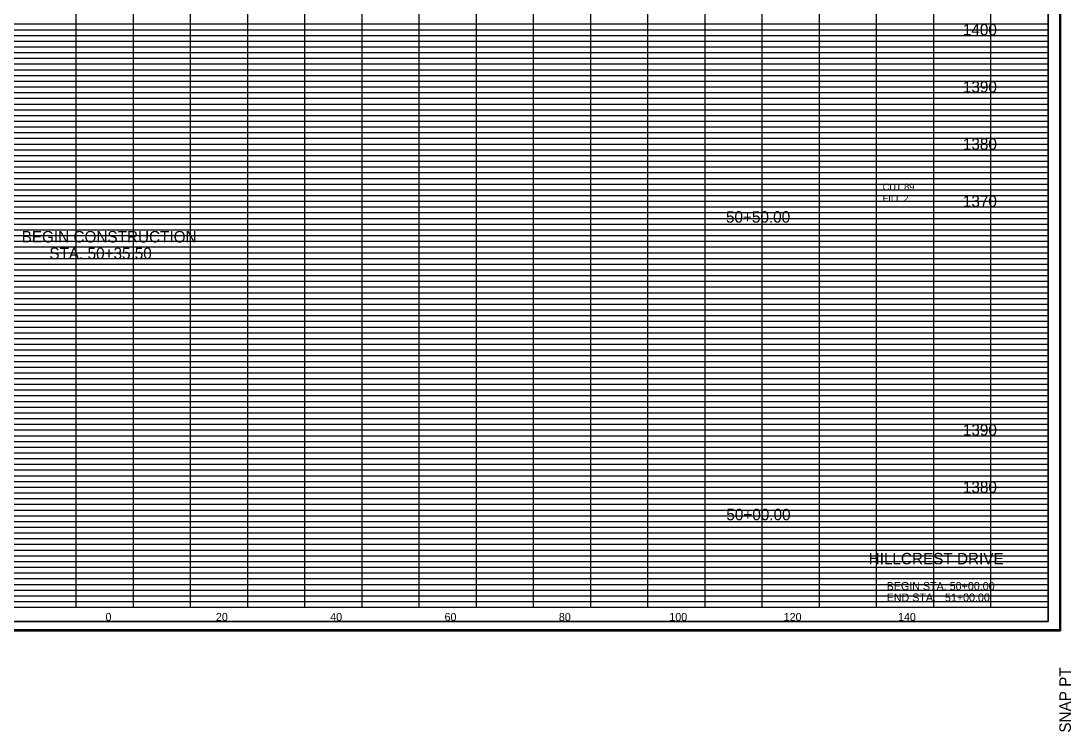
# Model space of a CAD drawing. Extents: x 980 to 1324, y 978 to 1497.
# Drawn here: x 1140.3 to 1324, y 978.2 to 1102.5 of the extents above; entities that cross this region are included whole.
import ezdxf

# ---------------------------------------------------------------- set-up
doc = ezdxf.new("R2010")
doc.units = 0
for name, color, linetype in [('DESIGN - SHEET - Corner Text', 7, 'Continuous'), ('DESIGN - SHEET - Light Grid', 7, 'Continuous'), ('DESIGN - SHEET - Linework', 7, 'Continuous'), ('DESIGN - SHEET - Plot Shape', 7, 'Continuous'), ('DESIGN - TYPICAL - Text', 7, 'Continuous')]:
    doc.layers.add(name, color=color, linetype=linetype)

# ---------------------------------------------------------------- blocks, each defined once
blk = doc.blocks.new('XSTSHT')
at = {"layer": 'DESIGN - SHEET - Light Grid'}
for p, q in [((8, 10.2), (16, 10.2)), ((16, 10.2), (24, 10.2)), ((24, 10.2), (32, 10.2)), ((8, 10.1), (16, 10.1)), ((16, 10.1), (24, 10.1)), ((24, 10.1), (32, 10.1)), ((8, 9.9), (16, 9.9)), ((8, 9.8), (16, 9.8)), ((16, 9.9), (24, 9.9)), ((16, 9.8), (24, 9.8)), ((24, 9.9), (32, 9.9)), ((24, 9.8), (32, 9.8)), ((8, 9.7), (16, 9.7)), ((8, 9.6), (16, 9.6)), ((16, 9.7), (24, 9.7)), ((16, 9.6), (24, 9.6)), ((24, 9.7), (32, 9.7)), ((24, 9.6), (32, 9.6)), ((8, 9.5), (16, 9.5)), ((8, 9.4), (16, 9.4)), ((16, 9.5), (24, 9.5)), ((16, 9.4), (24, 9.4)), ((24, 9.5), (32, 9.5)), ((24, 9.4), (32, 9.4)), ((8, 9.3), (16, 9.3)), ((8, 9.2), (16, 9.2)), ((16, 9.3), (24, 9.3)), ((16, 9.2), (24, 9.2)), ((24, 9.3), (32, 9.3)), ((24, 9.2), (32, 9.2)), ((8, 9.1), (16, 9.1)), ((16, 9.1), (24, 9.1)), ((24, 9.1), (32, 9.1)), ((8, 8.9), (16, 8.9)), ((16, 8.9), (24, 8.9)), ((24, 8.9), (32, 8.9)), ((8, 8.8), (16, 8.8)), ((8, 8.7), (16, 8.7)), ((16, 8.8), (24, 8.8)), ((16, 8.7), (24, 8.7)), ((24, 8.8), (32, 8.8)), ((24, 8.7), (32, 8.7)), ((8, 8.6), (16, 8.6)), ((8, 8.5), (16, 8.5)), ((16, 8.6), (24, 8.6)), ((16, 8.5), (24, 8.5)), ((24, 8.6), (32, 8.6)), ((24, 8.5), (32, 8.5)), ((8, 8.4), (16, 8.4)), ((8, 8.3), (16, 8.3)), ((16, 8.4), (24, 8.4)), ((16, 8.3), (24, 8.3)), ((24, 8.4), (32, 8.4)), ((24, 8.3), (32, 8.3)), ((8, 8.2), (16, 8.2)), ((8, 8.1), (16, 8.1)), ((16, 8.2), (24, 8.2)), ((16, 8.1), (24, 8.1)), ((24, 8.2), (32, 8.2)), ((24, 8.1), (32, 8.1)), ((8, 7.9), (16, 7.9)), ((16, 7.9), (24, 7.9)), ((24, 7.9), (32, 7.9)), ((8, 7.8), (16, 7.8)), ((16, 7.8), (24, 7.8)), ((24, 7.8), (32, 7.8)), ((8, 7.7), (16, 7.7)), ((8, 7.6), (16, 7.6)), ((16, 7.7), (24, 7.7)), ((16, 7.6), (24, 7.6)), ((24, 7.7), (32, 7.7)), ((24, 7.6), (32, 7.6)), ((8, 7.5), (16, 7.5)), ((8, 7.4), (16, 7.4)), ((16, 7.5), (24, 7.5)), ((16, 7.4), (24, 7.4)), ((24, 7.5), (32, 7.5)), ((24, 7.4), (32, 7.4)), ((8, 7.3), (16, 7.3)), ((8, 7.2), (16, 7.2)), ((16, 7.3), (24, 7.3)), ((16, 7.2), (24, 7.2)), ((24, 7.3), (32, 7.3)), ((24, 7.2), (32, 7.2)), ((8, 7.1), (16, 7.1)), ((16, 7.1), (24, 7.1)), ((24, 7.1), (32, 7.1)), ((8, 6.9), (16, 6.9)), ((8, 6.8), (16, 6.8)), ((16, 6.9), (24, 6.9)), ((16, 6.8), (24, 6.8)), ((24, 6.9), (32, 6.9)), ((24, 6.8), (32, 6.8)), ((8, 6.7), (16, 6.7)), ((16, 6.7), (24, 6.7)), ((24, 6.7), (32, 6.7)), ((8, 6.6), (16, 6.6)), ((8, 6.5), (16, 6.5)), ((16, 6.6), (24, 6.6)), ((16, 6.5), (24, 6.5)), ((24, 6.6), (32, 6.6)), ((24, 6.5), (32, 6.5)), ((8, 6.4), (16, 6.4)), ((8, 6.3), (16, 6.3)), ((16, 6.4), (24, 6.4)), ((16, 6.3), (24, 6.3)), ((24, 6.4), (32, 6.4)), ((24, 6.3), (32, 6.3)), ((8, 6.2), (16, 6.2)), ((8, 6.1), (16, 6.1)), ((16, 6.2), (24, 6.2)), ((16, 6.1), (24, 6.1)), ((24, 6.2), (32, 6.2)), ((24, 6.1), (32, 6.1)), ((8, 5.9), (16, 5.9)), ((16, 5.9), (24, 5.9)), ((24, 5.9), (32, 5.9)), ((8, 5.8), (16, 5.8)), ((8, 5.7), (16, 5.7)), ((16, 5.8), (24, 5.8)), ((16, 5.7), (24, 5.7)), ((24, 5.8), (32, 5.8)), ((24, 5.7), (32, 5.7)), ((8, 5.6), (16, 5.6)), ((16, 5.6), (24, 5.6)), ((24, 5.6), (32, 5.6)), ((8, 5.5), (16, 5.5)), ((8, 5.4), (16, 5.4)), ((16, 5.5), (24, 5.5)), ((16, 5.4), (24, 5.4)), ((24, 5.5), (32, 5.5)), ((24, 5.4), (32, 5.4)), ((8, 5.3), (16, 5.3)), ((8, 5.2), (16, 5.2)), ((16, 5.3), (24, 5.3)), ((16, 5.2), (24, 5.2)), ((24, 5.3), (32, 5.3)), ((24, 5.2), (32, 5.2)), ((8, 5.1), (16, 5.1)), ((16, 5.1), (24, 5.1)), ((24, 5.1), (32, 5.1)), ((8, 4.9), (16, 4.9)), ((8, 4.8), (16, 4.8)), ((16, 4.9), (24, 4.9)), ((16, 4.8), (24, 4.8)), ((24, 4.9), (32, 4.9)), ((24, 4.8), (32, 4.8)), ((8, 4.7), (16, 4.7)), ((8, 4.6), (16, 4.6)), ((16, 4.7), (24, 4.7)), ((16, 4.6), (24, 4.6)), ((24, 4.7), (32, 4.7)), ((24, 4.6), (32, 4.6)), ((8, 4.5), (16, 4.5)), ((16, 4.5), (24, 4.5)), ((24, 4.5), (32, 4.5)), ((8, 4.4), (16, 4.4)), ((8, 4.3), (16, 4.3)), ((16, 4.4), (24, 4.4)), ((16, 4.3), (24, 4.3)), ((24, 4.4), (32, 4.4)), ((24, 4.3), (32, 4.3)), ((8, 4.2), (16, 4.2)), ((8, 4.1), (16, 4.1)), ((16, 4.2), (24, 4.2)), ((16, 4.1), (24, 4.1)), ((24, 4.2), (32, 4.2)), ((24, 4.1), (32, 4.1)), ((8, 3.9), (16, 3.9)), ((16, 3.9), (24, 3.9)), ((24, 3.9), (32, 3.9)), ((8, 3.8), (16, 3.8)), ((8, 3.7), (16, 3.7)), ((16, 3.8), (24, 3.8)), ((16, 3.7), (24, 3.7)), ((24, 3.8), (32, 3.8)), ((24, 3.7), (32, 3.7)), ((8, 3.6), (16, 3.6)), ((8, 3.5), (16, 3.5)), ((16, 3.6), (24, 3.6)), ((16, 3.5), (24, 3.5)), ((24, 3.6), (32, 3.6)), ((24, 3.5), (32, 3.5)), ((8, 3.4), (16, 3.4)), ((16, 3.4), (24, 3.4)), ((24, 3.4), (32, 3.4)), ((8, 3.3), (16, 3.3)), ((8, 3.2), (16, 3.2)), ((16, 3.3), (24, 3.3)), ((16, 3.2), (24, 3.2)), ((24, 3.3), (32, 3.3)), ((24, 3.2), (32, 3.2)), ((8, 3.1), (16, 3.1)), ((16, 3.1), (24, 3.1)), ((24, 3.1), (32, 3.1)), ((8, 2.9), (16, 2.9)), ((8, 2.8), (16, 2.8)), ((16, 2.9), (24, 2.9)), ((16, 2.8), (24, 2.8)), ((24, 2.9), (32, 2.9)), ((24, 2.8), (32, 2.8)), ((8, 2.7), (16, 2.7)), ((8, 2.6), (16, 2.6)), ((16, 2.7), (24, 2.7)), ((16, 2.6), (24, 2.6)), ((24, 2.7), (32, 2.7)), ((24, 2.6), (32, 2.6)), ((8, 2.5), (16, 2.5)), ((8, 2.4), (16, 2.4)), ((16, 2.5), (24, 2.5)), ((16, 2.4), (24, 2.4)), ((24, 2.5), (32, 2.5)), ((24, 2.4), (32, 2.4)), ((8, 2.3), (16, 2.3)), ((16, 2.3), (24, 2.3)), ((24, 2.3), (32, 2.3)), ((8, 2.2), (16, 2.2)), ((8, 2.1), (16, 2.1)), ((16, 2.2), (24, 2.2)), ((16, 2.1), (24, 2.1)), ((24, 2.2), (32, 2.2)), ((24, 2.1), (32, 2.1)), ((8, 1.9), (16, 1.9)), ((16, 1.9), (24, 1.9)), ((24, 1.9), (32, 1.9)), ((8, 1.8), (16, 1.8)), ((8, 1.7), (16, 1.7)), ((16, 1.8), (24, 1.8)), ((16, 1.7), (24, 1.7)), ((24, 1.8), (32, 1.8)), ((24, 1.7), (32, 1.7)), ((8, 1.6), (16, 1.6)), ((8, 1.5), (16, 1.5)), ((16, 1.6), (24, 1.6)), ((16, 1.5), (24, 1.5)), ((24, 1.6), (32, 1.6)), ((24, 1.5), (32, 1.5)), ((8, 1.4), (16, 1.4)), ((8, 1.3), (16, 1.3)), ((16, 1.4), (24, 1.4)), ((16, 1.3), (24, 1.3)), ((24, 1.4), (32, 1.4)), ((24, 1.3), (32, 1.3)), ((8, 1.2), (16, 1.2)), ((16, 1.2), (24, 1.2)), ((24, 1.2), (32, 1.2)), ((8, 1.1), (16, 1.1)), ((16, 1.1), (24, 1.1)), ((24, 1.1), (32, 1.1)), ((8, 0.9), (16, 0.9)), ((8, 0.8), (16, 0.8)), ((16, 0.9), (24, 0.9)), ((16, 0.8), (24, 0.8)), ((24, 0.9), (32, 0.9)), ((24, 0.8), (32, 0.8)), ((8, 0.7), (16, 0.7)), ((8, 0.6), (16, 0.6)), ((16, 0.7), (24, 0.7)), ((16, 0.6), (24, 0.6)), ((24, 0.7), (32, 0.7)), ((24, 0.6), (32, 0.6)), ((8, 0.5), (16, 0.5)), ((8, 0.4), (16, 0.4)), ((16, 0.5), (24, 0.5)), ((16, 0.4), (24, 0.4)), ((24, 0.5), (32, 0.5)), ((24, 0.4), (32, 0.4)), ((8, 0.3), (16, 0.3)), ((8, 0.2), (16, 0.2)), ((16, 0.3), (24, 0.3)), ((16, 0.2), (24, 0.2)), ((24, 0.3), (32, 0.3)), ((24, 0.2), (32, 0.2)), ((8, 0.1), (16, 0.1)), ((16, 0.1), (24, 0.1)), ((24, 0.1), (32, 0.1))]:
    blk.add_line(p, q, dxfattribs=at)
at = {"layer": 'DESIGN - SHEET - Linework'}
for p, q in [((32.217, 21.414), (32.217, -0.414)), ((15, 0), (15, 21)), ((16, 0), (16, 21)), ((17, 0), (17, 21)), ((18, 0), (18, 21)), ((19, 0), (19, 21)), ((20, 0), (20, 21)), ((21, 0), (21, 21)), ((22, 0), (22, 21)), ((23, 0), (23, 21)), ((24, 0), (24, 21)), ((25, 0), (25, 21)), ((26, 0), (26, 21)), ((27, 0), (27, 21)), ((28, 0), (28, 20)), ((29, 0), (29, 20)), ((30, 0), (30, 20)), ((31, 0), (31, 20)), ((0, 10), (32, 10)), ((0, 9), (32, 9)), ((0, 8), (32, 8)), ((0, 7), (32, 7)), ((0, 6), (32, 6)), ((0, 5), (32, 5)), ((0, 4), (32, 4)), ((0, 3), (32, 3)), ((0, 2), (32, 2)), ((0, 1), (32, 1)), ((-1.823, -0.414), (32.217, -0.414))]:
    blk.add_line(p, q, dxfattribs=at)
blk.add_lwpolyline([(0, 21), (0, 0), (32, 0), (32, 21), (0, 21)], dxfattribs=at)
at = {"layer": 'DESIGN - SHEET - Plot Shape'}
for points in [[(-1.803, 21.394), (32.197, 21.394), (32.197, -0.394), (-1.803, -0.394)], [(-0.85, 21), (32, 21), (32, -0.25), (-0.85, -0.25)]]:
    blk.add_lwpolyline(points, close=True, dxfattribs=at)
at = {"layer": 'DESIGN - SHEET - Corner Text'}
blk.add_text('SNAP PT  ', height=0.2, rotation=90, dxfattribs=at).set_placement((32.397, -2.194))

msp = doc.modelspace()

# ---------------------------------------------------------------- linework, layer by layer
at = {"layer": 'DESIGN - SHEET - Plot Shape'}
msp.add_lwpolyline([(991.5, 997.5), (1320, 997.5), (1320, 1210), (991.5, 1210)], close=True, dxfattribs=at)

# ---------------------------------------------------------------- block references
at = {"layer": 'DESIGN - TYPICAL - Text', "xscale": 10, "yscale": 10}
msp.add_blockref('XSTSHT', (1000, 1000), dxfattribs=at)

# ---------------------------------------------------------------- texts
at = {"layer": 'DESIGN - SHEET - Corner Text'}
for s, height, p in [('HILLCREST DRIVE', 2, (1288.6, 1007.5)), ('BEGIN STA. 50+00.00', 1.4, (1291.75, 1003)), ('END STA.   51+00.00', 1.4, (1291.75, 1001))]:
    msp.add_text(s, height=height, dxfattribs=at).set_placement(p)
at = {"layer": 'DESIGN - TYPICAL - Text'}
for s, height, p in [('     1400     ', 2, (1301.37, 1100)), ('     1390     ', 2, (1301.37, 1090)), ('     1380     ', 2, (1301.37, 1080)), ('CUT 89', 1.2, (1291.06, 1072.89)), ('FILL 2', 1.2, (1291.06, 1070.89)), ('     1370     ', 2, (1301.37, 1070)), ('     50+50.00     ', 2, (1259.93, 1067.25)), ('BEGIN CONSTRUCTION', 2, (1140.44, 1063.79)), ('STA. 50+35.50', 2, (1145.29, 1060.89)), ('     1390     ', 2, (1301.37, 1030)), ('     1380     ', 2, (1301.37, 1020)), ('     50+00.00     ', 2, (1260, 1015.21)), ('     0     ', 1.4, (1152.51, 997.6)), ('     0     ', 1.4, (1152.51, 997.6)), ('     20     ', 1.4, (1171.82, 997.6)), ('     40     ', 1.4, (1191.82, 997.6)), ('     60     ', 1.4, (1211.82, 997.6)), ('     80     ', 1.4, (1231.82, 997.6)), ('     100     ', 1.4, (1251.14, 997.6)), ('     120     ', 1.4, (1271.14, 997.6)), ('     140     ', 1.4, (1291.14, 997.6))]:
    msp.add_text(s, height=height, dxfattribs=at).set_placement(p)

doc.saveas('drawing.dxf')
